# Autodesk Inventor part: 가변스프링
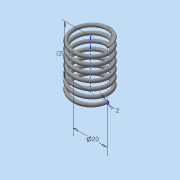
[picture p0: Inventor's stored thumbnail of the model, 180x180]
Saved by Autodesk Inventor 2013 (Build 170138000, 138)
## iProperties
Created: 2020-01
Part Number: 가변스프링
Material: 일반
Document SubType Name: Modeling
Designer: Administrator
Density: 1 g/cm^3
Author: Administrator
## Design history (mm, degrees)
sketch "스케치1"
  geometry: L1 (0, 0)-(10, 0); L2 (10, 0)-(10, 28.7); L3 (10, 28.7)-(0, 28.7); L4 (0, 28.7)-(0, 0); C1 r 1 at (10, 0)
  constraints: 8 end point, 2 parallel, 1 centre point, 1 coincident, 1 horizontal, 1 perpendicular
  dimensions: "d0" = 28.7 distance of L3.end L1.start (derived); "d1" = 20 diameter of L2 L4; "d2" = 2 diameter of C1
feature "코일1" sketch "스케치1" pitch "d3" = 10; turns "d5" = 7; dims "d4" = 28.7 (= d0), "d6" = 0, angle "d7" = 90 deg, angle "d8" = 90 deg, "d9" = 0, "d10" = 0
sketch "스케치2"
  geometry: L1 (-9, 0)-(-11, 0) reference; 1 further point
  constraints: 1 horizontal alignment
extrude "돌출1" cut sketch "스케치2" distance "d11" = 10; taper "d12" = 0 deg
node "작업 평면1"
sketch "스케치3"
  geometry: L1 (-1, 0)-(1, 0) reference; 1 further point
  constraints: 1 horizontal alignment
extrude "돌출2" cut sketch "스케치3" distance "d13" = 10; taper "d14" = 0 deg
node "솔리드1"
node "절단 모서리 투영1"
node "절단 모서리 투영2"
